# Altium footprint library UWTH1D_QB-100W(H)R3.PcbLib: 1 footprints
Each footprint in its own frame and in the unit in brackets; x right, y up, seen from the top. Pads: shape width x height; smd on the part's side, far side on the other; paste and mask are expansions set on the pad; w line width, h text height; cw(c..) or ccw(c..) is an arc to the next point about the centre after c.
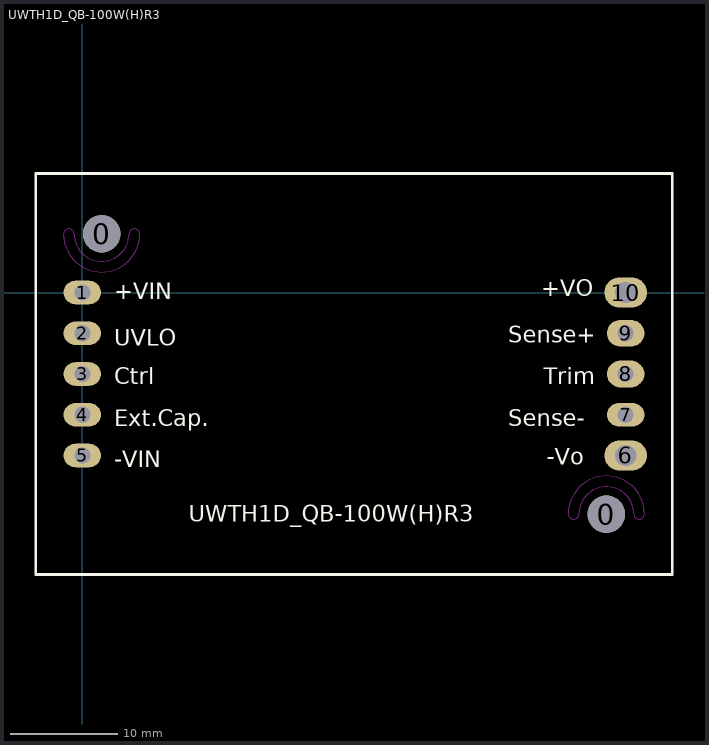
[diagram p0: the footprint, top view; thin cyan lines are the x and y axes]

## UWTH1D_QB-100W(H)R3 [mm]
pads (12):
  round 3.5 hole 3.5: 0(1.8,5.48) 0(49,-20.72)
  oval 3.5x2.2 hole 1.5: 1(0,0) 2(0,-3.81) 3(0,-7.62) 4(0,-11.43) 5(0,-15.24) 7(50.8,-11.43)
  oval 4x2.8 hole 2: 6(50.8,-15.24) 10(50.8,0)
  oval 3.5x2.5 hole 1.5: 8(50.8,-7.62) 9(50.8,-3.81)
Top Overlay:
  lines w0.254: 55.15,-26.37 -4.35,-26.37 -4.35,11.13 55.15,11.13 55.15,-26.36
  text "Ext.Cap." at 2.976,-12.523 h1.52
  text "-Vo" at 43.435,-16.106 h1.52
  text "Ctrl" at 2.979,-8.591 h1.52
  text "+VIN" at 2.976,-0.621 h1.52
  text "UVLO" at 2.976,-4.993 h1.52
  text "-VIN" at 2.976,-16.333 h1.52
  text "Sense+" at 39.82,-4.701 h1.52
  text "Trim" at 43.121,-8.566 h1.52
  text "+VO" at 42.918,-0.37 h1.52
  text "Sense-" at 39.82,-12.497 h1.52
  text "UWTH1D_QB-100W(H)R3" at 9.963,-21.457 h1.52
Keep-Out Layer:
  lines w0.025: -0.765,5.469 ccw(c1.8,5.48) 4.365,5.467 cw(c4.865,5.467) 5.365,5.467 ; -0.765,5.465 ccw(c-1.265,5.465) -1.765,5.465 ccw(c1.8,5.48) 5.365,5.462 ; 46.435,-20.709 cw(c49,-20.72) 51.565,-20.707 ccw(c52.065,-20.707) 52.565,-20.707 ; 46.435,-20.705 cw(c45.935,-20.705) 45.435,-20.705 cw(c49,-20.72) 52.565,-20.702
